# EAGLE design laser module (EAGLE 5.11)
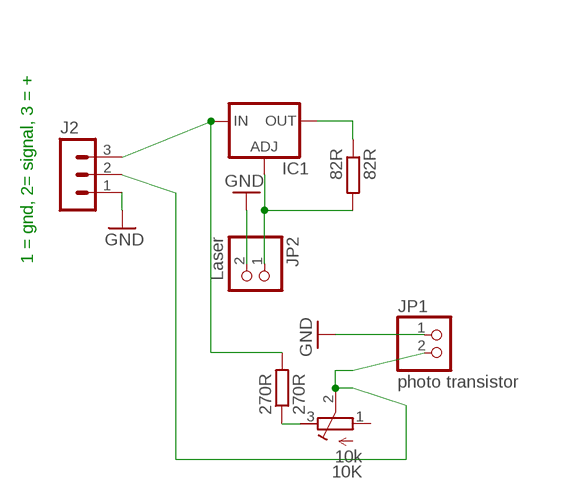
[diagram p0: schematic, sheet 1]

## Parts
10K  10k  R-TRIMM3339P  [RTRIM3339P]
82R  82R  R-EU_0207/2V  [0207/2V]
270R  270R  R-EU_0207/2V  [0207/2V]
IC1  LM317TS  [317TS]
J2  MA03-1  [MA03-1]
JP1  photo transistor  PINHD-1X2  [1X02]
JP2  Laser  PINHD-1X2  [1X02]

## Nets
GND: J2.1 JP1.1 JP2.2
N$1: 82R.2 IC1.1(ADJ) JP2.1
N$2: 82R.1 IC1.2(OUT)
N$3: 270R.2 IC1.3(IN) J2.3
N$4: 10K.2(S) J2.2 JP1.2
N$5: 10K.3(A) 270R.1
Unconnected: 10K.1(E)

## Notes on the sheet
- 1 = gnd, 2= signal, 3 = +

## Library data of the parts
10K = resistor:R-TRIMM: Trimm resistor
82R 270R = rcl:R-EU_: RESISTOR, European symbol
IC1 = v-reg:LM317TS: VOLTAGE REGULATOR
J2 = con-lstb:MA03-1: PIN HEADER; OC_FARNELL: unknown; OC_NEWARK: unknown
JP1 JP2 = pinhead:PINHD-1X2: PIN HEADER

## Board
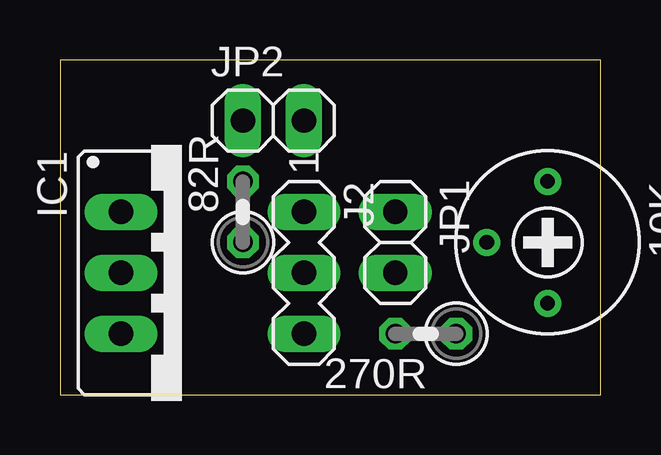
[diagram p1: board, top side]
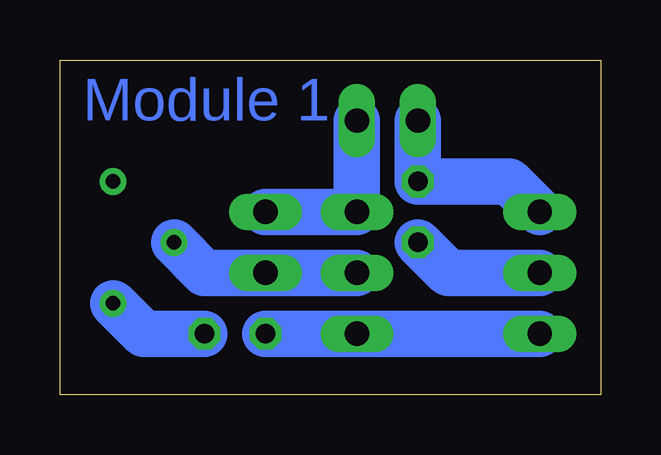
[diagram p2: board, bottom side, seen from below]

Size 22.53 x 13.96 mm. Coordinates in mm from the lower left corner, seen from the top.
Outline: 0,0 22.53,0 22.53,13.96 0,13.96 0,0
Copper layers (1*16): Top 0.035mm / dielectric 1.5mm / Bottom 0.035mm
Design rules "default": minimum track width 10mil, minimum drill 24mil, track to track 8mil, track to pad 8mil, pad to pad 8mil, via to via 8mil, smd to smd 8mil, copper to edge 40mil, drill to drill 8mil, minimum pad ring 10mil, minimum via ring 8mil, stop-mask expansion 4mil, vias tented up to drill 0mil, thermal gap 10mil

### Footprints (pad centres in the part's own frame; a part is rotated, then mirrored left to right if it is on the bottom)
RTRIM3339P = drill 0.61 round: 1 -2.54,0; 2 0,-2.54; 3 2.54,0
0207/2V = drill 0.813 octagon: 1 -1.27,0; 2 1.27,0
317TS = drill 1.016 long: 1 -2.54,-2.54; 2 0,-2.54; 3 2.54,-2.54
MA03-1 = drill 1.016 long: 1 -2.54,0; 2 0,0; 3 2.54,0
1X02 = drill 1.016 long: 1 -1.27,0; 2 1.27,0

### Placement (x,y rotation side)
10K  20.32,6.35 270 top
82R  7.62,7.62 90 top
270R  15.24,2.54 180 top
IC1  5.08,5.08 270 top
J2  10.16,5.08 270 top
JP1  13.97,6.35 270 top
JP2  8.89,11.43 0 top

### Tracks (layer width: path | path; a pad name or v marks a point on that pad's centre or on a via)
GND
  Bottom 1.93: JP2.2 J2.1 JP1.1
N$1
  Bottom 1.93: JP2.1 82R.2 3.81,8.89 IC1.1
N$2
  Bottom 1.93: IC1.2 6.35,5.08 82R.1
N$3
  Bottom 1.93: 270R.2 J2.3 IC1.3
N$4
  Bottom 1.93: J2.2 JP1.2 16.51,5.08 10K.2
N$5
  Bottom 1.93: 270R.1 19.05,2.54 10K.3

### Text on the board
Bottom: Module 1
